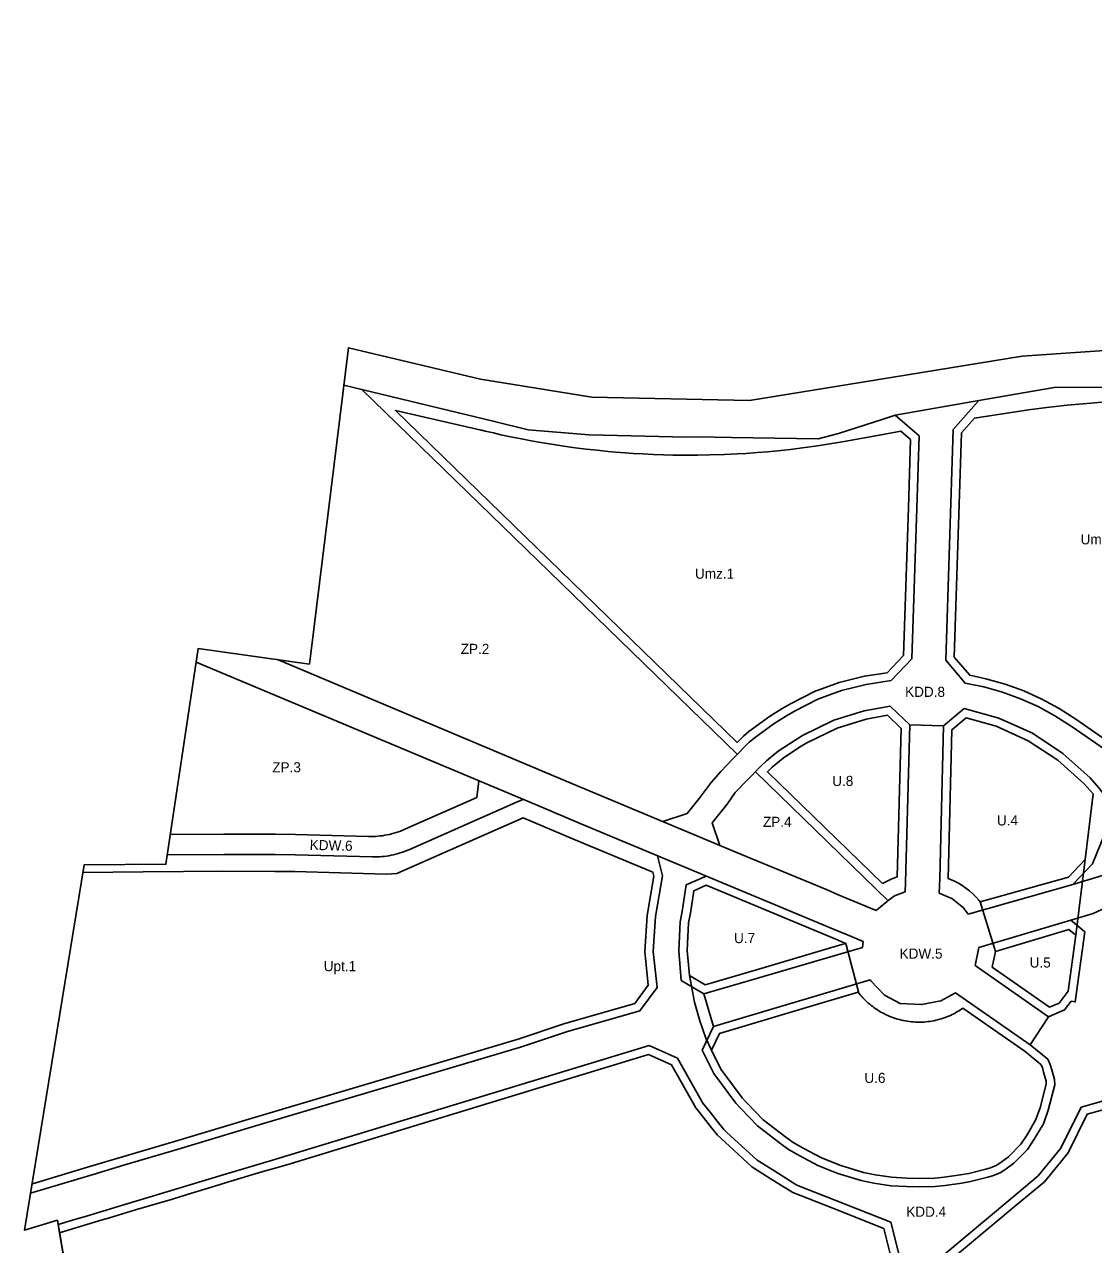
# Model space of a CAD drawing. Extents: x 7420092 to 7422347, y 5542930 to 5544880.
# Drawn here: x 7420112 to 7420746, y 5543382 to 5544105 of the extents above; entities that cross this region are included whole.
import ezdxf

# ---------------------------------------------------------------- set-up
doc = ezdxf.new("R2010")
doc.units = 0
for name, color, linetype in [('LIN_Granica Planu', 7, 'Continuous'), ('LIN_linie_rozgraniczajace', 7, 'Continuous'), ('LIN_linie_zabudowy_nieprzekraczalne', 7, 'Continuous'), ('LIN_linie_zabudowy_obowiazujace', 7, 'Continuous'), ('TXT_oznaczenia_przeznaczen', 7, 'Continuous')]:
    doc.layers.add(name, color=color, linetype=linetype)

msp = doc.modelspace()

# ---------------------------------------------------------------- linework, layer by layer
at = {"layer": 'LIN_Granica Planu'}
msp.add_lwpolyline([(7420168.76, 5543178.79), (7420131.86, 5543395.95), (7420112.28, 5543390.12), (7420147.7, 5543606.58), (7420196.16, 5543606.89), (7420215.32, 5543734.84), (7420281.17, 5543725.5), (7420281.92, 5543731.73), (7420304.35, 5543913.04), (7420382.59, 5543894.39), (7420448.49, 5543883.65), (7420541.88, 5543881.8), (7420609.94, 5543892.89), (7420703.36, 5543908.11), (7420803.92, 5543915.01)], dxfattribs=at)
at = {"layer": 'LIN_linie_rozgraniczajace'}
for p, q in [((7420312.14, 5543888.28), (7420534.64, 5543672.1)), ((7420415, 5543642.27), (7420214.08, 5543726.58)), ((7420440.68, 5543653.02), (7420262.14, 5543728.2)), ((7420656.88, 5543688.96), (7420636.89, 5543689.51)), ((7420545.38, 5543661.67), (7420623.9, 5543585.37)), ((7420634.17, 5543590.54), (7420634.33, 5543596.17)), ((7420654.27, 5543589.86), (7420654.58, 5543598.49)), ((7420663.87, 5543530.79), (7420708.14, 5543499.86)), ((7420718.99, 5543516.43), (7420708.14, 5543499.86))]:
    msp.add_line(p, q, dxfattribs=at)
for points in [[(7420158.31, 5543240.28), (7420133.14, 5543388.41), (7420131.86, 5543395.95), (7420112.28, 5543390.12), (7420147.7, 5543606.58), (7420196.16, 5543606.89), (7420215.32, 5543734.84), (7420281.17, 5543725.5), (7420281.92, 5543731.73), (7420304.35, 5543913.04), (7420382.59, 5543894.39), (7420448.49, 5543883.65), (7420541.88, 5543881.8), (7420609.94, 5543892.89), (7420703.36, 5543908.11), (7420803.92, 5543915.01), (7420873.43, 5543931.24), (7420922.3, 5543950.87), (7421004.88, 5544011.37), (7421076.71, 5544063.59), (7421101.18, 5544081.42), (7421115.83, 5544090.14), (7421144.5, 5544103.8), (7421171.72, 5544113.18)], [(7420912.19, 5543917.79), (7420902.52, 5543915.15), (7420900.3, 5543914.54), (7420852.75, 5543901.57), (7420838.42, 5543897.67), (7420831.16, 5543895.52), (7420814.42, 5543889.59), (7420722.4, 5543889.47), (7420677.79, 5543881.79), (7420628.09, 5543873.11), (7420621.11, 5543870.59), (7420594.67, 5543862.28), (7420582.5, 5543859.05), (7420531.28, 5543859.88), (7420511.29, 5543860.2)], [(7420301.6, 5543890.82), (7420390.88, 5543869.33), (7420410.83, 5543864.45), (7420446.9, 5543861.47), (7420504.79, 5543859.95), (7420511.29, 5543860.2)], [(7420814.42, 5543889.59), (7420822.05, 5543883), (7420806.29, 5543803.57), (7420801.32, 5543783.19), (7420769.49, 5543680.54), (7420752.7, 5543674.72), (7420732.38, 5543688.73), (7420722.81, 5543694.89), (7420712.81, 5543700.32), (7420702.43, 5543705.01), (7420691.74, 5543708.92), (7420680.79, 5543712.03), (7420669.64, 5543714.32), (7420658.13, 5543727.91), (7420662.48, 5543864.53), (7420677.79, 5543881.79)], [(7420628.09, 5543873.11), (7420642.31, 5543860.75), (7420641, 5543817.97), (7420638.14, 5543728.6), (7420625.78, 5543715.72), (7420610.97, 5543713.47), (7420596.44, 5543709.81), (7420582.33, 5543704.76), (7420568.92, 5543697.82), (7420563.73, 5543694.95), (7420556.55, 5543690.3), (7420544.66, 5543681.61), (7420541.74, 5543679.17), (7420532.19, 5543669.66), (7420524.99, 5543661.89), (7420519.2, 5543655.34), (7420511.99, 5543645.86), (7420504.95, 5543637.05), (7420490.5, 5543632.2)], [(7420671.41, 5543577.39), (7420733.53, 5543594.84), (7420751.71, 5543600.37), (7420759.48, 5543604.1), (7420765.91, 5543606.01), (7420778.21, 5543609.67), (7420919.22, 5543651.62), (7420939.1, 5543657.49), (7420959.05, 5543663.37), (7420961.07, 5543663.97), (7420982.8, 5543670.46), (7421004.61, 5543676.98), (7421033.68, 5543685.65), (7421060.34, 5543693.61), (7421215.88, 5543740.08)], [(7421227.01, 5543722.49), (7421006.8, 5543656.76), (7420985.44, 5543650.39), (7420963.59, 5543643.87), (7420952.76, 5543640.66), (7420942.13, 5543637.52), (7420920.53, 5543631.15), (7420891.44, 5543622.49), (7420763.03, 5543584.22), (7420753.28, 5543581.31), (7420745.56, 5543577.79), (7420732.21, 5543573.84), (7420677.82, 5543557.51)], [(7420524.22, 5543618.11), (7420519.7, 5543631.48), (7420528.55, 5543642.56), (7420533.42, 5543649.48), (7420540.83, 5543657.04), (7420548.25, 5543664.59), (7420551.99, 5543668.22), (7420558.9, 5543673.9), (7420568.87, 5543680.44), (7420573.37, 5543683.31), (7420591.94, 5543692.31), (7420609.9, 5543697.81), (7420625.31, 5543700.57)], [(7420625.31, 5543700.57), (7420636.89, 5543689.51), (7420634.33, 5543596.17)], [(7420654.58, 5543598.49), (7420656.88, 5543688.96), (7420669.1, 5543699.13)], [(7420669.1, 5543699.13), (7420689.68, 5543693.46), (7420709.45, 5543684.52), (7420727.59, 5543672.61), (7420743.66, 5543658.04), (7420748.79, 5543652.29), (7420757.27, 5543641.14), (7420751.92, 5543624.17), (7420745.05, 5543607.08), (7420733.53, 5543594.84)], [(7420381.51, 5543656.32), (7420380.29, 5543646.4), (7420337.69, 5543627.63)], [(7420533.79, 5543614.11), (7420442.67, 5543652.19), (7420440.68, 5543653.02)], [(7420407.74, 5543645.32), (7420405.26, 5543644.28), (7420340.12, 5543615.53)], [(7420415, 5543642.27), (7420441.56, 5543630.99), (7420538.08, 5543590.75)], [(7420316.13, 5543623.4), (7420272.83, 5543624.62), (7420260.8, 5543624.68), (7420230.44, 5543624.79), (7420198.81, 5543624.53)], [(7420337.69, 5543627.63), (7420336.42, 5543627.09), (7420335.14, 5543626.59), (7420333.84, 5543626.12), (7420332.53, 5543625.68), (7420331.2, 5543625.28), (7420329.86, 5543624.92), (7420328.51, 5543624.6), (7420327.15, 5543624.31), (7420325.78, 5543624.06), (7420324.41, 5543623.85), (7420323.03, 5543623.68), (7420321.65, 5543623.55), (7420320.26, 5543623.45), (7420318.88, 5543623.4), (7420317.51, 5543623.38), (7420316.13, 5543623.4)], [(7420318.55, 5543611.3), (7420272.69, 5543612.59), (7420260.8, 5543612.65), (7420230.53, 5543612.76), (7420197, 5543612.49)], [(7420340.12, 5543615.53), (7420338.86, 5543615), (7420337.57, 5543614.49), (7420336.27, 5543614.02), (7420334.96, 5543613.59), (7420333.63, 5543613.19), (7420332.29, 5543612.83), (7420330.93, 5543612.5), (7420329.57, 5543612.21), (7420328.2, 5543611.97), (7420326.83, 5543611.76), (7420325.45, 5543611.58), (7420324.07, 5543611.45), (7420322.69, 5543611.36), (7420321.31, 5543611.3), (7420319.93, 5543611.28), (7420318.55, 5543611.3)], [(7420487.08, 5543533.78), (7420484.81, 5543555.3), (7420486.13, 5543575.87), (7420490.26, 5543600.09), (7420487.44, 5543611.86)], [(7420616.94, 5543579.58), (7420594.09, 5543589.07), (7420587.8, 5543591.69), (7420533.79, 5543614.11)], [(7420501.48, 5543538.02), (7420499.93, 5543555.62), (7420500.82, 5543572.74), (7420502, 5543578.85), (7420504.33, 5543594.64), (7420516.22, 5543599.86)], [(7420609.22, 5543561.15), (7420604, 5543563.33), (7420598.93, 5543565.44), (7420596.38, 5543566.5), (7420538.08, 5543590.75)], [(7420634.17, 5543590.54), (7420627.83, 5543588.28), (7420623.76, 5543585.27), (7420616.94, 5543579.58)], [(7420671.41, 5543577.39), (7420668.41, 5543581.31), (7420661.75, 5543586.57), (7420654.27, 5543589.86)], [(7420732.51, 5543525.84), (7420734.9, 5543525.33), (7420740.51, 5543566.85), (7420732.21, 5543573.84)], [(7420609.22, 5543561.15), (7420608.84, 5543557.65)], [(7420514.91, 5543530.04), (7420547.45, 5543539.62), (7420591.28, 5543552.53), (7420608.84, 5543557.65)], [(7420677.82, 5543557.51), (7420675.63, 5543546.95), (7420718.99, 5543516.43)], [(7420708.14, 5543499.86), (7420718.55, 5543491.36), (7420720.11, 5543488.24), (7420720.96, 5543485.1), (7420722.54, 5543479.3), (7420722.77, 5543476.19), (7420718.84, 5543461.17), (7420715.97, 5543453.12), (7420710.59, 5543443.98), (7420706.56, 5543437.79), (7420698.57, 5543429.79), (7420693.96, 5543426.38), (7420690.72, 5543424.14), (7420686.39, 5543422.36), (7420683.15, 5543421.39), (7420672.81, 5543418.81), (7420667.66, 5543417.87), (7420657.76, 5543416.44), (7420651.91, 5543415.95), (7420642.67, 5543415.66), (7420634.83, 5543415.87), (7420625.55, 5543416.43), (7420615.5, 5543417.96), (7420608.11, 5543419.43), (7420594.24, 5543423.59), (7420582.4, 5543428.44), (7420571.61, 5543434.02), (7420565.04, 5543437.89), (7420560.36, 5543441.14), (7420546.65, 5543451.8), (7420536.97, 5543461.89), (7420536.16, 5543462.74), (7420533.76, 5543465.24), (7420520.71, 5543482.84), (7420513.79, 5543496.66), (7420520.49, 5543510.75), (7420514.91, 5543530.04), (7420501.48, 5543538.02)], [(7420520.49, 5543510.75), (7420551.06, 5543519.86), (7420576.15, 5543527.32), (7420613.33, 5543538.39), (7420613.8, 5543537.9)], [(7420613.8, 5543537.9), (7420621.94, 5543529.31), (7420631.13, 5543524.45), (7420643.86, 5543523.71), (7420655.31, 5543525.88), (7420663.87, 5543530.79)], [(7420487.08, 5543533.78), (7420476.97, 5543520.05), (7420433.45, 5543507.55), (7420406.29, 5543498.54), (7420246.67, 5543451.01), (7420234.17, 5543447.28), (7420202.7, 5543437.91), (7420171.86, 5543428.73), (7420152.98, 5543423.11), (7420115.87, 5543412.06)], [(7420718.99, 5543516.43), (7420728.53, 5543520.56), (7420732.51, 5543525.84)], [(7420132.3, 5543393.38), (7420142.81, 5543396.54), (7420148.98, 5543398.39), (7420167.83, 5543404.05), (7420198.66, 5543413.32), (7420230.09, 5543422.76), (7420242.61, 5543426.52), (7420259.32, 5543431.54), (7420268.32, 5543434.25), (7420482.37, 5543499.41), (7420499.14, 5543491.93), (7420514.32, 5543465.32), (7420518.57, 5543459.92), (7420522.7, 5543454.65), (7420526.62, 5543449.69), (7420528.27, 5543448.16), (7420546.38, 5543431.5), (7420556.8, 5543424.98), (7420569.87, 5543416.79), (7420593.04, 5543407.66), (7420625.59, 5543394.82), (7420630.74, 5543374.45)], [(7420738.42, 5543462.96), (7420753.04, 5543467.05), (7420783.56, 5543445.39), (7420835.54, 5543408.49), (7420847.28, 5543400.16), (7420893.77, 5543367.15), (7420901.19, 5543361.89), (7420908.53, 5543356.67), (7420924.29, 5543345.45), (7420968.07, 5543314.27), (7420994.05, 5543295.77)], [(7420655.75, 5543374.54), (7420696.68, 5543408.66), (7420713, 5543422.29), (7420726.39, 5543438.67), (7420738.42, 5543462.96)]]:
    msp.add_lwpolyline(points, dxfattribs=at)
at = {"layer": 'LIN_linie_zabudowy_nieprzekraczalne'}
for points in [[(7420811.32, 5543885.66), (7420803.76, 5543884.75), (7420780.7, 5543882.91), (7420753.06, 5543880.93), (7420739.63, 5543879.85), (7420730.1, 5543878.95), (7420719.53, 5543877.8), (7420707.2, 5543876.28), (7420675.21, 5543871.35), (7420667.42, 5543862.56), (7420663.19, 5543729.67), (7420672.34, 5543718.87), (7420681.98, 5543716.89), (7420693.28, 5543713.68), (7420704.32, 5543709.64), (7420715.03, 5543704.81), (7420725.36, 5543699.19), (7420735.15, 5543692.89), (7420753.45, 5543680.27), (7420765.46, 5543684.44), (7420796.5, 5543784.52), (7420801.41, 5543804.65), (7420816.58, 5543881.12), (7420811.32, 5543885.66)], [(7420534.59, 5543679.11), (7420538.36, 5543682.87), (7420541.58, 5543685.55), (7420553.72, 5543694.42), (7420561.16, 5543699.24), (7420566.56, 5543702.23), (7420580.33, 5543709.36), (7420594.98, 5543714.6), (7420609.98, 5543718.38), (7420623.35, 5543720.41), (7420633.2, 5543730.68), (7420636, 5543818.13), (7420637.24, 5543858.53), (7420631.49, 5543863.53), (7420615.54, 5543860.65), (7420597.93, 5543857.47), (7420587.1, 5543855.65), (7420580.78, 5543854.7), (7420574.61, 5543853.84), (7420566.19, 5543852.8), (7420558.58, 5543851.97), (7420552.49, 5543851.39), (7420546.4, 5543850.88), (7420539.81, 5543850.42), (7420534.51, 5543850.1), (7420527, 5543849.75), (7420518.24, 5543849.47), (7420511.32, 5543849.36), (7420503.54, 5543849.34), (7420496.53, 5543849.43), (7420490.97, 5543849.56), (7420485.03, 5543849.77), (7420478.73, 5543850.07), (7420472.93, 5543850.41), (7420468.2, 5543850.74), (7420462.58, 5543851.18), (7420458.1, 5543851.58), (7420451.53, 5543852.23), (7420445.04, 5543852.96), (7420440.12, 5543853.57), (7420437.29, 5543853.94), (7420431.88, 5543854.69), (7420425.7, 5543855.62), (7420419.51, 5543856.63), (7420412.48, 5543857.87), (7420406.74, 5543858.96), (7420400.27, 5543860.27), (7420394.62, 5543861.47), (7420390.14, 5543862.48), (7420385.35, 5543863.6), (7420383.21, 5543864.12), (7420382.88, 5543864.15), (7420332.11, 5543875.85), (7420534.59, 5543679.11)], [(7420407.79, 5543634.47), (7420376.29, 5543620.59), (7420333.01, 5543601.52), (7420326.65, 5543601.1), (7420272.47, 5543602.62), (7420260.7, 5543602.68), (7420230.49, 5543602.79), (7420182.71, 5543602.41), (7420146.96, 5543602.05)], [(7420116.98, 5543417.61), (7420151.55, 5543427.9), (7420170.43, 5543433.52), (7420201.27, 5543442.7), (7420232.74, 5543452.07), (7420245.24, 5543455.8), (7420404.79, 5543503.31)], [(7420413.4, 5543473.19), (7420269.77, 5543429.46), (7420260.76, 5543426.75), (7420252.99, 5543424.56), (7420232.67, 5543418.47), (7420228.34, 5543417.15), (7420208.06, 5543411.04), (7420200.1, 5543408.53), (7420178.02, 5543402.06), (7420162.69, 5543397.41), (7420158.31, 5543396.1), (7420138.13, 5543389.99), (7420133.74, 5543388.59), (7420133.13, 5543388.41)]]:
    msp.add_lwpolyline(points, dxfattribs=at)
at = {"layer": 'LIN_linie_zabudowy_obowiazujace'}
for points in [[(7420620.71, 5543595.45), (7420623, 5543596.76), (7420625.38, 5543597.91), (7420627.82, 5543598.92), (7420629.42, 5543599.46), (7420631.83, 5543687.43), (7420623.69, 5543695.2), (7420611.08, 5543692.94), (7420593.78, 5543687.64), (7420575.81, 5543678.93), (7420571.59, 5543676.24), (7420561.87, 5543669.87), (7420555.32, 5543664.49), (7420552.49, 5543661.73), (7420620.71, 5543595.45)], [(7420719.58, 5543522.13), (7420725.33, 5543524.62), (7420730.73, 5543531.78), (7420735.19, 5543564.8), (7420740.76, 5543609.82), (7420745.4, 5543648.57), (7420740.1, 5543654.51), (7420724.52, 5543668.65), (7420707.04, 5543680.12), (7420687.98, 5543688.74), (7420670.29, 5543693.62), (7420661.82, 5543686.57), (7420659.58, 5543598.45), (7420660.9, 5543597.97), (7420663.32, 5543596.9), (7420665.67, 5543595.69), (7420667.94, 5543594.33), (7420670.11, 5543592.83), (7420672.19, 5543591.19), (7420674.16, 5543589.43), (7420676.02, 5543587.55), (7420677.75, 5543585.56), (7420678.5, 5543584.58), (7420687.56, 5543555.21), (7420685.65, 5543546.01), (7420719.58, 5543522.13)], [(7420404.84, 5543503.33), (7420431.97, 5543512.33), (7420473.95, 5543524.39), (7420481.9, 5543535.18), (7420479.79, 5543555.2), (7420481.16, 5543576.45), (7420485.16, 5543599.92), (7420484.61, 5543602.21), (7420437.68, 5543621.77), (7420407.79, 5543634.47)], [(7420678.5, 5543584.58), (7420730.84, 5543599.28), (7420740.76, 5543609.82)], [(7420714.56, 5543488.17), (7420705.12, 5543495.87), (7420668.34, 5543521.57), (7420665.71, 5543519.93), (7420664.78, 5543519.38), (7420663.84, 5543518.84), (7420662.87, 5543518.33), (7420661.88, 5543517.84), (7420660.87, 5543517.36), (7420659.84, 5543516.91), (7420658.8, 5543516.49), (7420657.73, 5543516.08), (7420656.66, 5543515.7), (7420655.56, 5543515.35), (7420654.45, 5543515.02), (7420653.32, 5543514.72), (7420652.19, 5543514.45), (7420651.04, 5543514.2), (7420649.87, 5543513.99), (7420648.7, 5543513.8), (7420647.52, 5543513.64), (7420646.33, 5543513.52), (7420645.14, 5543513.42), (7420643.93, 5543513.36), (7420642.73, 5543513.33), (7420641.52, 5543513.33), (7420640.31, 5543513.37), (7420639.1, 5543513.44), (7420637.89, 5543513.54), (7420636.68, 5543513.67), (7420635.48, 5543513.83), (7420634.28, 5543514.03), (7420633.09, 5543514.26), (7420631.9, 5543514.52), (7420630.72, 5543514.81), (7420629.56, 5543515.13), (7420628.4, 5543515.49), (7420627.26, 5543515.87), (7420626.13, 5543516.28), (7420625.01, 5543516.72), (7420623.91, 5543517.19), (7420622.83, 5543517.69), (7420621.77, 5543518.21), (7420620.72, 5543518.76), (7420619.69, 5543519.33), (7420618.68, 5543519.93), (7420617.7, 5543520.55), (7420616.73, 5543521.19), (7420615.79, 5543521.85), (7420614.87, 5543522.53), (7420613.97, 5543523.23), (7420613.1, 5543523.94), (7420612.25, 5543524.68), (7420611.42, 5543525.42), (7420610.62, 5543526.19), (7420609.85, 5543526.96), (7420609.1, 5543527.75), (7420608.37, 5543528.55), (7420607.68, 5543529.36), (7420606.72, 5543530.51), (7420599.01, 5543559.99), (7420597.01, 5543560.82), (7420594.46, 5543561.88), (7420516.27, 5543594.42), (7420508.87, 5543591.17), (7420506.93, 5543578.01), (7420505.8, 5543572.13), (7420504.94, 5543555.71), (7420506.24, 5543541.01), (7420509.21, 5543525.12), (7420512.46, 5543514.02), (7420515.99, 5543503.86), (7420519.35, 5543496.72), (7420524.99, 5543485.47), (7420537.59, 5543468.47), (7420539.77, 5543466.2), (7420540.58, 5543465.35), (7420550.01, 5543455.52), (7420563.32, 5543445.17), (7420567.74, 5543442.1), (7420574.03, 5543438.4), (7420584.5, 5543432.98), (7420595.91, 5543428.31), (7420609.32, 5543424.29), (7420616.36, 5543422.89), (7420626.08, 5543421.41), (7420635.05, 5543420.87), (7420642.66, 5543420.66), (7420651.62, 5543420.94), (7420657.19, 5543421.41), (7420666.85, 5543422.81), (7420671.75, 5543423.7), (7420681.83, 5543426.21), (7420684.72, 5543427.08), (7420688.32, 5543428.56), (7420691.05, 5543430.45), (7420695.3, 5543433.59), (7420702.65, 5543440.95), (7420706.34, 5543446.61), (7420711.42, 5543455.25), (7420714.06, 5543462.65), (7420717.72, 5543476.65), (7420717.59, 5543478.45), (7420716.13, 5543483.79), (7420715.41, 5543486.45), (7420714.56, 5543488.17)], [(7420735.19, 5543564.8), (7420731.06, 5543568.27), (7420687.56, 5543555.21)], [(7420506.24, 5543541.01), (7420515.59, 5543535.45), (7420546.04, 5543544.42), (7420589.87, 5543557.33), (7420596.6, 5543559.29), (7420599.01, 5543559.99)], [(7420606.26, 5543531.07), (7420577.58, 5543522.53), (7420552.49, 5543515.07), (7420524.05, 5543506.59), (7420519.35, 5543496.72)], [(7420595.12, 5543334.02), (7420597.39, 5543337.19), (7420600.71, 5543341.79), (7420615.6, 5543361.76), (7420625.6, 5543374.4), (7420621.37, 5543391.11), (7420591.21, 5543403.01), (7420567.61, 5543412.31), (7420554.15, 5543420.74), (7420543.34, 5543427.51), (7420524.88, 5543444.49), (7420522.94, 5543446.29), (7420518.77, 5543451.56), (7420514.64, 5543456.83), (7420510.16, 5543462.52), (7420495.61, 5543488.03), (7420482.04, 5543494.08), (7420413.4, 5543473.19)], [(7420802.74, 5543425.64), (7420780.67, 5543441.31), (7420752.09, 5543461.59), (7420741.91, 5543458.74), (7420730.62, 5543435.94), (7420716.57, 5543418.76), (7420699.88, 5543404.82), (7420656.63, 5543368.76), (7420645.82, 5543359.76), (7420639.42, 5543353.75), (7420634.07, 5543347.4), (7420629.42, 5543342.3), (7420622.32, 5543334.52), (7420600.86, 5543304.87), (7420590.88, 5543290.84), (7420579.39, 5543273.99)]]:
    msp.add_lwpolyline(points, dxfattribs=at)

# ---------------------------------------------------------------- texts
at = {"layer": 'TXT_oznaczenia_przeznaczen'}
for s, p in [('Umz.2', (7420738.05, 5543796.48)), ('Umz.1', (7420509.59, 5543776.14)), ('ZP.2', (7420370.79, 5543731.54)), ('ZP.3', (7420259.14, 5543661.38)), ('U.8', (7420590.9, 5543653.28)), ('ZP.4', (7420549.87, 5543629.03)), ('U.4', (7420688.47, 5543629.9)), ('U.7', (7420532.73, 5543560.18)), ('U.5', (7420707.87, 5543545.68)), ('Upt.1', (7420289.64, 5543543.54)), ('U.6', (7420609.96, 5543477.29))]:
    msp.add_text(s, height=6, dxfattribs=at).set_placement(p)
for s, rotation, p in [('KDD.8', 360, (7420634.08, 5543706.09)), ('KDW.6', 358.74651, (7420281.27, 5543615.41)), ('KDW.5', 360, (7420630.82, 5543550.96)), ('KDD.4', 360, (7420634.77, 5543397.99))]:
    msp.add_text(s, height=6, rotation=rotation, dxfattribs=at).set_placement(p)

doc.saveas('drawing.dxf')
